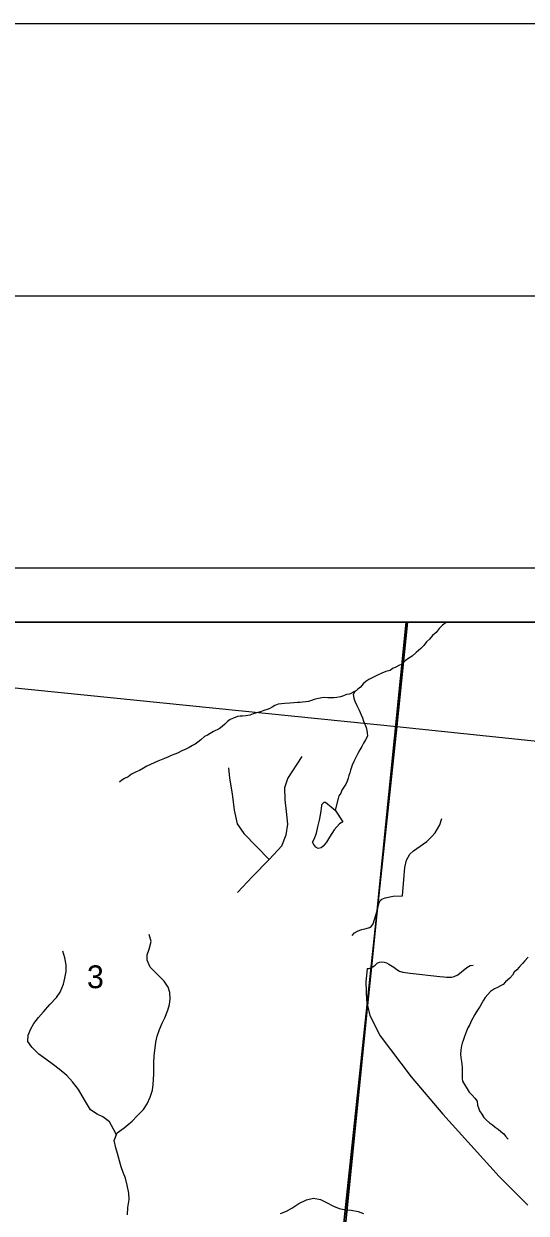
# Model space of a CAD drawing. Extents: x 0 to 43.4, y -8.1 to 22.
# Drawn here: x 3.361 to 4.286, y 19.813 to 22 of the extents above; entities that cross this region are included whole.
import ezdxf

# ---------------------------------------------------------------- set-up
doc = ezdxf.new("R2010")
doc.units = 0
for name, color, linetype in [('GM_X_Corporation', 7, 'Continuous'), ('GM_X_Minor_Lake', 7, 'Continuous'), ('GM_X_Minor_River', 7, 'Continuous'), ('GM_X_Section_Text', 7, 'Continuous'), ('GM_X_State_Route', 7, 'Continuous'), ('GM_X_Township_Road', 7, 'Continuous'), ('SH_Border', 7, 'Continuous'), ('SH_Cut_Line', 7, 'Continuous'), ('SH_Data', 7, 'Continuous')]:
    doc.layers.add(name, color=color, linetype=linetype)

msp = doc.modelspace()

# ---------------------------------------------------------------- linework, layer by layer
at = {"layer": 'GM_X_Corporation'}
for points in [[(8.9, 20.9), (2.1, 20.9), (2.1, 18.7697), (2.2164, 18.6602), (2.3024, 18.5637), (2.4531, 18.3722), (2.5091, 18.2757), (2.5944, 18.1569), (2.6477, 18.0826), (2.8129, 17.7895), (2.9482, 17.5993), (3.2529, 17.1207), (3.3535, 16.9292), (3.4766, 16.7366), (3.5579, 16.6418), (3.619, 16.5459), (3.7774, 16.2543), (3.8686, 16.1561), (3.9643, 16.0791), (4.2564, 15.9373), (4.3533, 15.9108)], [(3.918, 19.4441), (3.9936, 20.1953), (4.0006, 20.2658), (4.0111, 20.3696), (4.0645, 20.9), (2.1, 20.9), (2.1, 18.7697)], [(8.9, 20.9), (4.0645, 20.9), (4.0111, 20.3696), (4.0006, 20.2658), (3.9936, 20.1953), (3.918, 19.4441), (3.8667, 18.9338), (3.8234, 18.5529), (3.8126, 18.3973), (3.8023, 18.3182), (3.7454, 17.7286), (3.744, 17.7149), (3.7921, 17.7096), (3.9407, 17.6938), (4.0716, 17.683), (4.1644, 17.6753), (4.3821, 17.6581)]]:
    msp.add_lwpolyline(points, dxfattribs=at)
for points in [[(4.0674, 20.9), (3.0509, 20.9), (3.042, 20.8098), (4.0476, 20.7082)], [(5.0731, 20.9), (4.0674, 20.9), (4.0476, 20.7082), (5.0456, 20.604)], [(4.0476, 20.7082), (3.9403, 19.703), (2.9428, 19.8144), (3.042, 20.8098)], [(4.0476, 20.7082), (5.0456, 20.604), (4.9462, 19.5972), (3.9403, 19.703)]]:
    msp.add_lwpolyline(points, close=True, dxfattribs=at)
at = {"layer": 'GM_X_Minor_Lake'}
for points in [[(3.8955, 20.5012), (3.8996, 20.5121), (3.9022, 20.5238), (3.9052, 20.5359), (3.9078, 20.5488), (3.9096, 20.562), (3.9097, 20.5647), (3.9101, 20.5654), (3.914, 20.5688), (3.9163, 20.5687), (3.9338, 20.5542)], [(3.9338, 20.5542), (3.9484, 20.5325), (3.9422, 20.5293), (3.9324, 20.5181), (3.9237, 20.5047), (3.9181, 20.4953), (3.9119, 20.4883), (3.908, 20.4849), (3.9026, 20.4836), (3.8985, 20.4859), (3.8945, 20.491), (3.8923, 20.4956), (3.8955, 20.5012)]]:
    msp.add_lwpolyline(points, dxfattribs=at)
at = {"layer": 'GM_X_Minor_River'}
for points in [[(4.1386, 20.9), (4.138, 20.8993), (4.1317, 20.8942), (4.1254, 20.888), (4.1199, 20.8809), (4.1132, 20.8755), (4.1077, 20.8684), (4.1022, 20.8637), (4.097, 20.857), (4.0915, 20.8515), (4.0829, 20.8442), (4.0755, 20.8376), (4.0696, 20.8337), (4.0626, 20.8286), (4.0567, 20.8223), (4.0521, 20.8206), (4.0447, 20.8163), (4.0397, 20.8145), (4.0351, 20.8113), (4.0274, 20.8093), (4.0197, 20.8061), (4.012, 20.8026), (4.0031, 20.798), (3.9962, 20.7944), (3.9907, 20.7908), (3.9856, 20.7864), (3.9809, 20.7805), (3.9758, 20.7769), (3.9695, 20.7714), (3.9671, 20.7669), (3.9684, 20.76), (3.9701, 20.7546), (3.9736, 20.7465), (3.9783, 20.738), (3.9818, 20.7295), (3.9842, 20.7237), (3.9863, 20.718), (3.9888, 20.7122), (3.9908, 20.706), (3.9925, 20.7007), (3.9931, 20.6961), (3.9933, 20.6904), (3.9897, 20.6837), (3.9861, 20.6777), (3.9828, 20.6713), (3.9792, 20.6654), (3.9759, 20.6587), (3.9714, 20.6497), (3.9686, 20.6437), (3.9653, 20.637), (3.9623, 20.628), (3.961, 20.6227), (3.9593, 20.6178), (3.958, 20.6133), (3.9563, 20.6077), (3.9535, 20.6021), (3.9502, 20.5965), (3.9466, 20.5909), (3.9445, 20.5853), (3.941, 20.5808), (3.9393, 20.5759)], [(3.9711, 20.7727), (3.9607, 20.7675), (3.9549, 20.7666), (3.9496, 20.7645), (3.9438, 20.7628), (3.9373, 20.7611), (3.9316, 20.7605), (3.9206, 20.7609), (3.9153, 20.7615), (3.9096, 20.7609), (3.9004, 20.7589), (3.8954, 20.7576), (3.8908, 20.7558), (3.885, 20.7541), (3.8801, 20.7532), (3.874, 20.753), (3.869, 20.7524), (3.8645, 20.7522), (3.858, 20.7517), (3.8504, 20.7508), (3.8416, 20.7503), (3.8294, 20.7492), (3.8233, 20.7468), (3.8182, 20.7435), (3.8136, 20.741), (3.809, 20.7393), (3.8029, 20.7376), (3.7967, 20.7348), (3.789, 20.7331), (3.7833, 20.7311), (3.7771, 20.729), (3.7695, 20.7277), (3.7638, 20.7272), (3.7592, 20.727), (3.7546, 20.7264), (3.7469, 20.7232), (3.7411, 20.7207), (3.7357, 20.7175), (3.731, 20.7124), (3.7259, 20.7083), (3.7204, 20.704), (3.7104, 20.6986), (3.7042, 20.695), (3.6992, 20.6922), (3.6938, 20.6897), (3.6871, 20.6835), (3.6813, 20.6791), (3.6766, 20.6758), (3.6715, 20.673), (3.6653, 20.6694), (3.6592, 20.6662), (3.6522, 20.663), (3.6441, 20.6591), (3.6391, 20.6574), (3.6326, 20.6546), (3.6272, 20.6521), (3.6202, 20.6493), (3.6141, 20.6468), (3.6079, 20.644), (3.601, 20.6412), (3.5944, 20.6384), (3.5875, 20.6352), (3.5817, 20.6316), (3.5739, 20.627), (3.5678, 20.6245), (3.5596, 20.6202), (3.553, 20.6155), (3.5465, 20.6127), (3.5414, 20.6091), (3.537, 20.6056)], [(3.9393, 20.5759), (3.9393, 20.5759), (3.9338, 20.5542)], [(3.5521, 19.8101), (3.5525, 19.8234), (3.5552, 19.8382), (3.5544, 19.85), (3.5514, 19.8645), (3.548, 19.8775), (3.5441, 19.8879), (3.5406, 19.8986), (3.5371, 19.9098), (3.5333, 19.9228), (3.5302, 19.9331), (3.5275, 19.9469), (3.5329, 19.9608), (3.5457, 19.9703), (3.5605, 19.9825), (3.5699, 19.9921), (3.5812, 20.0039), (3.5884, 20.014), (3.5937, 20.0268), (3.5978, 20.0396), (3.5993, 20.0498), (3.5995, 20.0593), (3.6002, 20.0692), (3.6005, 20.0794), (3.6004, 20.0893), (3.6012, 20.103), (3.6022, 20.1124), (3.6042, 20.1276), (3.6068, 20.1385), (3.6109, 20.151), (3.6158, 20.1626), (3.6207, 20.1727), (3.6264, 20.1866), (3.629, 20.1972), (3.6304, 20.2071), (3.6296, 20.2189), (3.6265, 20.2288), (3.6196, 20.2401), (3.6066, 20.2526), (3.5937, 20.2655), (3.5884, 20.2782), (3.5879, 20.2881), (3.592, 20.2986), (3.5958, 20.3126), (3.5917, 20.3256)], [(3.5315, 19.9572), (3.5263, 19.9679), (3.519, 19.9814), (3.5064, 19.9905), (3.4963, 19.9953), (3.484, 20.0033), (3.4749, 20.0184), (3.4684, 20.0288), (3.4615, 20.0408), (3.4505, 20.0548), (3.4402, 20.0665), (3.4261, 20.0783), (3.4157, 20.0858), (3.402, 20.0965), (3.3886, 20.1056), (3.3757, 20.1185), (3.3687, 20.129), (3.3694, 20.1404), (3.374, 20.1524), (3.3796, 20.1621), (3.3882, 20.1733), (3.3977, 20.1833), (3.4091, 20.197), (3.4212, 20.21), (3.4279, 20.2197), (3.4341, 20.2343), (3.4367, 20.2456), (3.4389, 20.2577), (3.4389, 20.2699), (3.4366, 20.2829), (3.4332, 20.2948)], [(4.2891, 20.2838), (4.2832, 20.2775), (4.2788, 20.2723), (4.2725, 20.2653), (4.2682, 20.2609), (4.2631, 20.2562), (4.2602, 20.2506), (4.2551, 20.2454), (4.2473, 20.2385), (4.2433, 20.234), (4.2383, 20.2312), (4.2325, 20.2283), (4.2271, 20.2255), (4.2201, 20.2208), (4.215, 20.2156), (4.2099, 20.2101), (4.2067, 20.2049), (4.2046, 20.2004), (4.201, 20.1941), (4.1958, 20.1867), (4.1909, 20.1785), (4.1844, 20.1665), (4.1816, 20.1602), (4.1783, 20.1538), (4.1758, 20.1482), (4.1721, 20.1381), (4.1695, 20.1306), (4.1675, 20.1261), (4.1666, 20.1212), (4.1652, 20.1136), (4.1645, 20.1056), (4.1654, 20.0992), (4.1663, 20.0923), (4.1673, 20.0873), (4.1675, 20.0812), (4.1677, 20.0668), (4.1675, 20.0611), (4.1681, 20.0557), (4.1803, 20.0359), (4.1862, 20.03), (4.1913, 20.0249), (4.1953, 20.0195), (4.1962, 20.0118), (4.1979, 20.0068), (4.1996, 20.0014), (4.204, 19.9956), (4.2076, 19.9894), (4.212, 19.9851), (4.2182, 19.9795), (4.2234, 19.9755), (4.2282, 19.9712), (4.2341, 19.9676), (4.2389, 19.9636), (4.2441, 19.9592), (4.2477, 19.9546), (4.2521, 19.9491)], [(3.8336, 19.8124), (3.8443, 19.817), (3.8544, 19.8224), (3.8671, 19.8308), (3.881, 19.838), (3.894, 19.8407), (3.9072, 19.8384), (3.917, 19.8336), (3.9312, 19.8263), (3.9417, 19.8218), (3.9538, 19.8196), (3.9636, 19.8189), (3.9765, 19.8166), (3.9862, 19.8126)]]:
    msp.add_lwpolyline(points, dxfattribs=at)
at = {"layer": 'GM_X_State_Route'}
msp.add_lwpolyline([(3.9932, 20.263), (3.9906, 20.2377), (3.9917, 20.2046), (3.9938, 20.1948), (3.9979, 20.1764), (4.0167, 20.1395), (4.0741, 20.0638), (4.132, 19.9956), (4.2358, 19.8805), (4.2884, 19.828)], dxfattribs=at)
at = {"layer": 'GM_X_Township_Road'}
for points in [[(3.7545, 20.4029), (3.7821, 20.432), (3.8129, 20.4637), (3.8359, 20.4884), (3.844, 20.5088), (3.8472, 20.5286), (3.8445, 20.5516), (3.8418, 20.5731), (3.8413, 20.5961), (3.8467, 20.6122), (3.8735, 20.6529)], [(3.7379, 20.632), (3.7395, 20.6133), (3.7448, 20.5843), (3.7481, 20.5543), (3.7539, 20.5291), (3.7663, 20.5114), (3.8129, 20.4637)], [(4.014, 20.3788), (4.0153, 20.3837), (4.0171, 20.3879), (4.0198, 20.3906), (4.0263, 20.3931), (4.0408, 20.3958), (4.0579, 20.3969), (4.0609, 20.4338), (4.0622, 20.449), (4.0652, 20.4622), (4.0713, 20.4733), (4.0779, 20.4796), (4.1025, 20.4968), (4.1113, 20.5049), (4.1181, 20.5123), (4.1265, 20.5273), (4.1304, 20.539)], [(4.0007, 20.3411), (4.0037, 20.3452), (4.0114, 20.3691), (4.014, 20.3788)], [(3.9653, 20.3239), (3.9699, 20.3284), (3.9749, 20.3319), (3.9794, 20.3334), (3.9829, 20.3347), (3.9913, 20.3368), (3.9974, 20.3385), (4.0001, 20.3403), (4.0007, 20.3411)], [(4.0023, 20.2658), (4.0036, 20.2664), (4.0055, 20.2678), (4.0075, 20.2694), (4.0093, 20.2713), (4.0116, 20.2727), (4.0156, 20.2746), (4.02, 20.2752), (4.0239, 20.2748), (4.0284, 20.2735), (4.0329, 20.2712), (4.0422, 20.2653), (4.0476, 20.2613), (4.0523, 20.2584), (4.0588, 20.2561), (4.0721, 20.2547), (4.1265, 20.2483), (4.1337, 20.2476), (4.1387, 20.247), (4.1431, 20.247), (4.1479, 20.2471), (4.1531, 20.2484), (4.1595, 20.2514), (4.1761, 20.2648), (4.1823, 20.2686), (4.1878, 20.2692)], [(3.9932, 20.263), (3.9964, 20.2634), (4.0009, 20.2652), (4.0023, 20.2658)]]:
    msp.add_lwpolyline(points, dxfattribs=at)
at = {"layer": 'SH_Border'}
msp.add_lwpolyline([(1.5, 21.5), (33.5, 21.5), (33.5, 0.5), (1.5, 0.5)], close=True, dxfattribs=at)
at = {"layer": 'SH_Cut_Line'}
msp.add_lwpolyline([(0, 0), (34, 0), (34, 22), (0, 22)], close=True, dxfattribs=at)
at = {"layer": 'SH_Data'}
for p, q in [((2, 21), (9, 21)), ((2.1, 20.9), (8.9, 20.9))]:
    msp.add_line(p, q, dxfattribs=at)

# ---------------------------------------------------------------- texts
at = {"layer": 'GM_X_Section_Text'}
msp.add_text('3', height=0.0419, rotation=0, dxfattribs=at).set_placement((3.4773, 20.2269))

doc.saveas('drawing.dxf')
